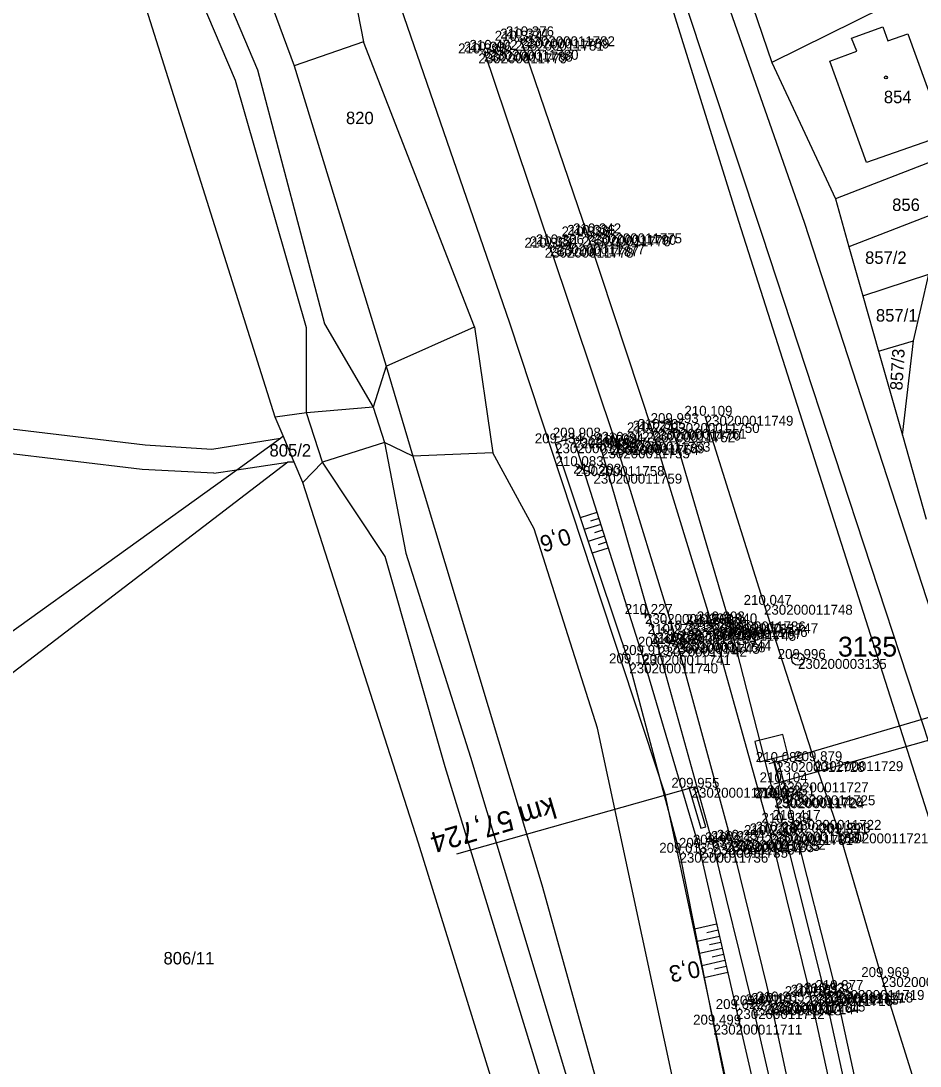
# Model space of a CAD drawing. Extents: x -563148 to -561712, y -1182311 to -1179502.
# Drawn here: x -562800.9 to -562692.4, y -1179961.9 to -1179835.6 of the extents above; entities that cross this region are included whole.
import ezdxf

# ---------------------------------------------------------------- set-up
doc = ezdxf.new("R2010")
doc.units = 0
for name, color, linetype in [('Vrstva 1', 7, 'Continuous'), ('Vrstva 14', 7, 'Continuous'), ('Vrstva 23', 7, 'Continuous'), ('Vrstva 4', 7, 'Continuous'), ('Vrstva 48', 7, 'Continuous'), ('Vrstva 49', 7, 'Continuous'), ('Vrstva 53', 7, 'Continuous'), ('Vrstva 55', 7, 'Continuous'), ('Vrstva 56', 7, 'Continuous'), ('Vrstva 57', 7, 'Continuous'), ('Vrstva 60', 7, 'Continuous'), ('Vrstva 61', 7, 'Continuous'), ('Vrstva 63', 7, 'Continuous'), ('Vrstva 7', 7, 'Continuous'), ('Vrstva 9', 7, 'Continuous')]:
    doc.layers.add(name, color=color, linetype=linetype)

msp = doc.modelspace()

# ---------------------------------------------------------------- linework, layer by layer
at = {"layer": 'Vrstva 1'}
for points in [[(-562740.6, -1179837.77), (-562732.51, -1179861.48), (-562724.71, -1179885.12), (-562717.35, -1179909.07), (-562710.47, -1179933.75), (-562705.64, -1179953.24), (-562700.21, -1179978.17), (-562696.2, -1179999.76), (-562692.55, -1180023.18), (-562689.41, -1180047.36), (-562687.1, -1180067.31), (-562684.6, -1180089.77), (-562682.01, -1180113.42)], [(-562745.01, -1179839.35), (-562737.06, -1179862.87), (-562729.09, -1179886.66), (-562721.74, -1179910.68), (-562715.17, -1179934.68), (-562710.39, -1179954.23), (-562705.02, -1179979.2), (-562701.02, -1180000.75), (-562697.43, -1180023.66), (-562694.26, -1180047.81), (-562691.92, -1180067.92), (-562689.44, -1180090.3), (-562686.84, -1180113.86)]]:
    msp.add_lwpolyline(points, dxfattribs=at)
at = {"layer": 'Vrstva 14'}
msp.add_lwpolyline([(-562708.48, -1179929.16), (-562709.81, -1179929.52), (-562709.06, -1179932.48), (-562703.91, -1179952.98), (-562698.53, -1179977.59), (-562694.4, -1179999.84), (-562690.74, -1180023.29), (-562687.63, -1180047.31), (-562685.27, -1180067.34), (-562682.92, -1180089.43), (-562680.17, -1180114.48), (-562679.62, -1180119.47), (-562678.23, -1180119.28), (-562678.8, -1180114.3), (-562681.54, -1180089.23), (-562683.88, -1180067.22), (-562686.25, -1180047.12), (-562689.37, -1180023.01), (-562693.01, -1179999.73), (-562697.19, -1179977.32), (-562702.55, -1179952.67), (-562707.74, -1179932.13), (-562708.48, -1179929.16)], dxfattribs=at)
at = {"layer": 'Vrstva 23'}
msp.add_line((-562733.93, -1179889.41), (-562731.8, -1179890.32), dxfattribs=at)
at = {"layer": 'Vrstva 4'}
for points in [[(-562722.45, -1179884.21), (-562715.38, -1179908.39), (-562709.97, -1179929.42)], [(-562683.72, -1180156.67), (-562685.94, -1180137.11), (-562688.4, -1180114.59), (-562691.08, -1180090.75), (-562693.51, -1180068.13), (-562695.85, -1180048.01), (-562699.08, -1180023.86), (-562701.31, -1180009.06), (-562702.78, -1180000.96), (-562706.81, -1179979.53), (-562712.56, -1179954.53), (-562717.35, -1179935.12), (-562723.98, -1179911.21), (-562730.87, -1179887.27)]]:
    msp.add_lwpolyline(points, dxfattribs=at)
at = {"layer": 'Vrstva 48'}
for p, q in [((-562731.39, -1179895.01), (-562733.4, -1179895.65)), ((-562731.16, -1179895.73), (-562732.16, -1179896.04)), ((-562730.93, -1179896.44), (-562732.92, -1179897.07)), ((-562730.48, -1179897.87), (-562732.44, -1179898.49)), ((-562730.71, -1179897.16), (-562731.69, -1179897.47)), ((-562730.03, -1179899.3), (-562731.96, -1179899.91)), ((-562730.25, -1179898.59), (-562731.22, -1179898.9)), ((-562716.93, -1179944.73), (-562719.59, -1179945.33)), ((-562716.6, -1179946.19), (-562719.3, -1179946.8)), ((-562716.76, -1179945.46), (-562718.1, -1179945.76)), ((-562716.43, -1179946.92), (-562717.79, -1179947.23)), ((-562716.26, -1179947.65), (-562719.01, -1179948.28)), ((-562716.09, -1179948.38), (-562717.48, -1179948.7)), ((-562715.93, -1179949.11), (-562718.72, -1179949.75)), ((-562715.76, -1179949.84), (-562717.17, -1179950.16)), ((-562715.59, -1179950.57), (-562718.43, -1179951.22))]:
    msp.add_line(p, q, dxfattribs=at)
at = {"layer": 'Vrstva 49'}
for points in [[(-562718.37, -1179883.33), (-562711.21, -1179906.16), (-562705.11, -1179925.04), (-562702.08, -1179933.76), (-562697.02, -1179951.11), (-562689.45, -1179975.3), (-562684.23, -1179997.89)], [(-562734.26, -1179885.96), (-562736.43, -1179886.65), (-562727.47, -1179913.23), (-562721.41, -1179936.1), (-562717.31, -1179956.85), (-562712.51, -1179980.34), (-562708.84, -1179979.83)], [(-562734.26, -1179885.96), (-562725.93, -1179912.22), (-562719.03, -1179935.5), (-562714.59, -1179954.97), (-562708.84, -1179979.83)]]:
    msp.add_lwpolyline(points, dxfattribs=at)
at = {"layer": 'Vrstva 53'}
for p, q in [((-562726.49, -1179820.62), (-562714.28, -1179859.84)), ((-562741.88, -1179872.14), (-562755.69, -1179832.1)), ((-562714.28, -1179859.84), (-562686.66, -1179946.58)), ((-562723.16, -1179929.01), (-562741.88, -1179872.14)), ((-562708.95, -1179995.64), (-562723.16, -1179929.01))]:
    msp.add_line(p, q, dxfattribs=at)
at = {"layer": 'Vrstva 55'}
for p, q in [((-562770.21, -1179883.48), (-562789.53, -1179822.31)), ((-562771.87, -1179830.41), (-562767.94, -1179841.07)), ((-562712.55, -1179833.93), (-562710.25, -1179840.66)), ((-562696.76, -1179834), (-562710.25, -1179840.66)), ((-562700.64, -1179837.73), (-562696.86, -1179836.37)), ((-562696.86, -1179836.37), (-562696.27, -1179838.05)), ((-562699.99, -1179839.29), (-562700.64, -1179837.73)), ((-562696.27, -1179838.05), (-562693.84, -1179837.19)), ((-562693.84, -1179837.19), (-562689.44, -1179849.44)), ((-562759.58, -1179838.16), (-562767.94, -1179841.07)), ((-562746.18, -1179872.58), (-562759.58, -1179838.16)), ((-562703.26, -1179840.49), (-562699.99, -1179839.29)), ((-562767.94, -1179841.07), (-562756.81, -1179877.33)), ((-562710.25, -1179840.66), (-562702.59, -1179857.13)), ((-562698.83, -1179852.76), (-562703.26, -1179840.49)), ((-562689.44, -1179849.44), (-562698.83, -1179852.76)), ((-562687.51, -1179851.29), (-562702.59, -1179857.13)), ((-562702.59, -1179857.13), (-562700.96, -1179862.91)), ((-562689.54, -1179858.51), (-562700.96, -1179862.91)), ((-562700.96, -1179862.91), (-562699.28, -1179868.83)), ((-562699.28, -1179868.83), (-562691.31, -1179866.24)), ((-562693.16, -1179874.28), (-562691.31, -1179866.24)), ((-562699.28, -1179868.83), (-562697.39, -1179875.51)), ((-562756.81, -1179877.33), (-562746.18, -1179872.58)), ((-562697.39, -1179875.51), (-562693.16, -1179874.28)), ((-562694.51, -1179885.66), (-562693.16, -1179874.28)), ((-562697.39, -1179875.51), (-562694.51, -1179885.66)), ((-562868.6, -1179877.08), (-562785.92, -1179886.82)), ((-562756.81, -1179877.33), (-562753.62, -1179888.19)), ((-562786.27, -1179889.8), (-562868.86, -1179880.06)), ((-562769.26, -1179885.74), (-562770.21, -1179883.48)), ((-562769.57, -1179886.05), (-562769.26, -1179885.74)), ((-562767.92, -1179888.92), (-562769.26, -1179885.74)), ((-562694.51, -1179885.66), (-562691.64, -1179895.8)), ((-562785.92, -1179886.82), (-562777.87, -1179887.35)), ((-562777.87, -1179887.35), (-562769.57, -1179886.05)), ((-562774.86, -1179889.85), (-562769.57, -1179886.05)), ((-562743.96, -1179887.8), (-562753.62, -1179888.19)), ((-562753.62, -1179888.19), (-562738.04, -1179939.96)), ((-562738.97, -1179896.97), (-562743.96, -1179887.8)), ((-562768.68, -1179888.92), (-562835.68, -1179940.17)), ((-562774.86, -1179889.85), (-562768.68, -1179888.92)), ((-562767.92, -1179888.92), (-562768.68, -1179888.92)), ((-562766.88, -1179891.39), (-562767.92, -1179888.92)), ((-562839.45, -1179936.26), (-562774.86, -1179889.85)), ((-562777.64, -1179890.27), (-562786.27, -1179889.8)), ((-562777.64, -1179890.27), (-562774.86, -1179889.85)), ((-562752.94, -1179934.93), (-562766.88, -1179891.39)), ((-562731.33, -1179921.05), (-562738.97, -1179896.97)), ((-562716.52, -1179989.81), (-562731.33, -1179921.05)), ((-562736.47, -1179988), (-562752.94, -1179934.93)), ((-562738.04, -1179939.96), (-562723.97, -1179990.65))]:
    msp.add_line(p, q, dxfattribs=at)
at = {"layer": 'Vrstva 56'}
for p, q in [((-562788.49, -1179803.34), (-562772.35, -1179841.57)), ((-562775.02, -1179842.84), (-562791.27, -1179804.7)), ((-562720.72, -1179818.86), (-562706.35, -1179859.95)), ((-562711.42, -1179861.45), (-562725.13, -1179820.2)), ((-562761.97, -1179825.83), (-562759.58, -1179838.16)), ((-562772.35, -1179841.57), (-562764.29, -1179872.23)), ((-562766.45, -1179872.71), (-562775.02, -1179842.84)), ((-562706.35, -1179859.95), (-562678.76, -1179945.02)), ((-562683.71, -1179946), (-562711.42, -1179861.45)), ((-562766.44, -1179882.98), (-562766.45, -1179872.71)), ((-562764.29, -1179872.23), (-562758.38, -1179882.28)), ((-562746.18, -1179872.58), (-562743.96, -1179887.8)), ((-562756.81, -1179877.33), (-562758.38, -1179882.28)), ((-562766.44, -1179882.98), (-562770.21, -1179883.48)), ((-562758.38, -1179882.28), (-562766.44, -1179882.98)), ((-562764.52, -1179888.92), (-562766.44, -1179882.98)), ((-562758.38, -1179882.28), (-562757.03, -1179886.57)), ((-562757.03, -1179886.57), (-562764.52, -1179888.92)), ((-562753.62, -1179888.19), (-562757.03, -1179886.57)), ((-562757.03, -1179886.57), (-562754.44, -1179899.9)), ((-562764.52, -1179888.92), (-562766.88, -1179891.39)), ((-562756.93, -1179900.31), (-562764.52, -1179888.92)), ((-562749.69, -1179925.73), (-562756.93, -1179900.31)), ((-562754.44, -1179899.9), (-562746.63, -1179924.55)), ((-562746.63, -1179924.55), (-562733.41, -1179968.62)), ((-562736.38, -1179969.25), (-562749.69, -1179925.73))]:
    msp.add_line(p, q, dxfattribs=at)
at = {"layer": 'Vrstva 57'}
msp.add_circle((-562696.49, -1179842.47), 0.175, dxfattribs=at)
at = {"layer": 'Vrstva 60'}
for p, q in [((-562740.6, -1179837.77), (-562740.6, -1179837.77)), ((-562739.92, -1179837.5), (-562739.92, -1179837.5)), ((-562741.27, -1179838.03), (-562741.27, -1179838.03)), ((-562745.69, -1179839.57), (-562745.69, -1179839.57)), ((-562745.01, -1179839.35), (-562745.01, -1179839.35)), ((-562744.32, -1179839.14), (-562744.32, -1179839.14)), ((-562733.2, -1179861.67), (-562733.2, -1179861.67)), ((-562732.51, -1179861.48), (-562732.51, -1179861.48)), ((-562731.82, -1179861.3), (-562731.82, -1179861.3)), ((-562737.68, -1179863.03), (-562737.68, -1179863.03)), ((-562737.06, -1179862.87), (-562737.06, -1179862.87)), ((-562736.29, -1179862.63), (-562736.29, -1179862.63)), ((-562722.45, -1179884.21), (-562722.45, -1179884.21)), ((-562718.37, -1179883.33), (-562718.37, -1179883.33)), ((-562725.4, -1179885.33), (-562725.4, -1179885.33)), ((-562724.71, -1179885.12), (-562724.71, -1179885.12)), ((-562724.01, -1179884.92), (-562724.01, -1179884.92)), ((-562736.43, -1179886.65), (-562736.43, -1179886.65)), ((-562734.26, -1179885.96), (-562734.26, -1179885.96)), ((-562729.79, -1179886.85), (-562729.79, -1179886.85)), ((-562729.09, -1179886.66), (-562729.09, -1179886.66)), ((-562728.39, -1179886.47), (-562728.39, -1179886.47)), ((-562730.87, -1179887.27), (-562730.87, -1179887.27)), ((-562733.93, -1179889.41), (-562733.93, -1179889.41)), ((-562731.8, -1179890.32), (-562731.8, -1179890.32)), ((-562711.21, -1179906.16), (-562711.21, -1179906.16)), ((-562725.57, -1179907.26), (-562725.57, -1179907.26)), ((-562716.88, -1179908.16), (-562716.88, -1179908.16)), ((-562715.38, -1179908.39), (-562715.38, -1179908.39)), ((-562722.8, -1179909.67), (-562722.8, -1179909.67)), ((-562721.42, -1179909.26), (-562721.42, -1179909.26)), ((-562718.29, -1179908.5), (-562718.29, -1179908.5)), ((-562718.04, -1179909.29), (-562718.04, -1179909.29)), ((-562717.35, -1179909.07), (-562717.35, -1179909.07)), ((-562716.66, -1179908.84), (-562716.66, -1179908.84)), ((-562722.44, -1179910.87), (-562722.44, -1179910.87)), ((-562721.74, -1179910.68), (-562721.74, -1179910.68)), ((-562721.05, -1179910.5), (-562721.05, -1179910.5)), ((-562725.93, -1179912.22), (-562725.93, -1179912.22)), ((-562723.98, -1179911.21), (-562723.98, -1179911.21)), ((-562727.47, -1179913.23), (-562727.47, -1179913.23)), ((-562707.11, -1179912.69), (-562707.11, -1179912.69)), ((-562709.75, -1179925.14), (-562709.75, -1179925.14)), ((-562705.11, -1179925.04), (-562705.11, -1179925.04)), ((-562719.95, -1179928.25), (-562719.95, -1179928.25)), ((-562709.29, -1179927.59), (-562709.29, -1179927.59)), ((-562709.97, -1179929.42), (-562709.97, -1179929.42)), ((-562709.81, -1179929.52), (-562709.81, -1179929.52)), ((-562708.48, -1179929.16), (-562708.48, -1179929.16)), ((-562707.74, -1179932.13), (-562707.74, -1179932.13)), ((-562709.78, -1179933.56), (-562709.78, -1179933.56)), ((-562709.06, -1179932.48), (-562709.06, -1179932.48)), ((-562715.88, -1179934.82), (-562715.88, -1179934.82)), ((-562715.17, -1179934.68), (-562715.17, -1179934.68)), ((-562714.46, -1179934.53), (-562714.46, -1179934.53)), ((-562711.17, -1179933.95), (-562711.17, -1179933.95)), ((-562710.47, -1179933.75), (-562710.47, -1179933.75)), ((-562702.08, -1179933.76), (-562702.08, -1179933.76)), ((-562721.41, -1179936.1), (-562721.41, -1179936.1)), ((-562719.03, -1179935.5), (-562719.03, -1179935.5)), ((-562717.35, -1179935.12), (-562717.35, -1179935.12)), ((-562697.02, -1179951.11), (-562697.02, -1179951.11)), ((-562702.55, -1179952.67), (-562702.55, -1179952.67)), ((-562706.34, -1179953.41), (-562706.34, -1179953.41)), ((-562705.64, -1179953.24), (-562705.64, -1179953.24)), ((-562704.93, -1179953.07), (-562704.93, -1179953.07)), ((-562703.91, -1179952.98), (-562703.91, -1179952.98)), ((-562714.59, -1179954.97), (-562714.59, -1179954.97)), ((-562712.56, -1179954.53), (-562712.56, -1179954.53)), ((-562711.1, -1179954.39), (-562711.1, -1179954.39)), ((-562710.39, -1179954.23), (-562710.39, -1179954.23)), ((-562709.68, -1179954.06), (-562709.68, -1179954.06)), ((-562717.31, -1179956.85), (-562717.31, -1179956.85))]:
    msp.add_line(p, q, dxfattribs=at)
at = {"layer": 'Vrstva 63'}
msp.add_line((-562707.16, -1179912.69), (-562707.06, -1179912.69), dxfattribs=at)
msp.add_circle((-562707.11, -1179912.69), 0.756, dxfattribs=at)
at = {"layer": 'Vrstva 7'}
for p, q in [((-562725.57, -1179906.76), (-562725.57, -1179907.76)), ((-562726.07, -1179907.26), (-562725.07, -1179907.26)), ((-562709.29, -1179927.59), (-562674.34, -1179917.65)), ((-562710.02, -1179927.77), (-562708.57, -1179927.4))]:
    msp.add_line(p, q, dxfattribs=at)
msp.add_lwpolyline([(-562709.29, -1179927.59), (-562710.03, -1179924.68), (-562708.33, -1179924.25), (-562708.94, -1179921.83), (-562712.33, -1179922.68), (-562711.72, -1179925.1), (-562710.03, -1179924.68)], dxfattribs=at)
at = {"layer": 'Vrstva 9'}
for p, q in [((-562709.75, -1179925.14), (-562675.7, -1179915.15)), ((-562710.04, -1179925.21), (-562710.62, -1179925.36)), ((-562709.46, -1179925.06), (-562710.04, -1179925.21)), ((-562710.04, -1179925.21), (-562708.81, -1179930.06)), ((-562708.23, -1179929.91), (-562709.46, -1179925.06)), ((-562719.95, -1179928.25), (-562748.33, -1179936.25)), ((-562720.24, -1179928.34), (-562720.81, -1179928.51)), ((-562719.66, -1179928.17), (-562720.24, -1179928.34)), ((-562720.24, -1179928.34), (-562718.82, -1179933.13)), ((-562718.24, -1179932.96), (-562719.66, -1179928.17)), ((-562708.81, -1179930.06), (-562708.23, -1179929.91)), ((-562718.82, -1179933.13), (-562718.24, -1179932.96))]:
    msp.add_line(p, q, dxfattribs=at)

# ---------------------------------------------------------------- texts
at = {"layer": 'Vrstva 48'}
for s, rotation, p in [('0,6', 197.5951, (-562734.91, -1179896.84)), ('0,3', 191.1734, (-562719.16, -1179949.1))]:
    msp.add_text(s, height=2, rotation=rotation, dxfattribs=at).set_placement(p)
at = {"layer": 'Vrstva 57'}
for s, p in [('854', (-562696.74, -1179845.58)), ('820', (-562761.68, -1179848.11)), ('856', (-562695.74, -1179858.59)), ('857/2', (-562699.01, -1179864.98)), ('857/1', (-562697.7, -1179871.95)), ('805/2', (-562770.91, -1179888.25)), ('806/11', (-562783.71, -1179949.58))]:
    msp.add_text(s, height=1.5, dxfattribs=at).set_placement(p)
msp.add_text('857/3', height=1.5, rotation=86.6336, dxfattribs=at).set_placement((-562694.51, -1179880.29))
at = {"layer": 'Vrstva 60'}
for s, p in [('230200011789', (-562740.6, -1179838.97)), ('230200011782', (-562739.92, -1179838.7)), ('230200011781', (-562741.27, -1179839.23)), ('230200011779', (-562745.69, -1179840.77)), ('230200011788', (-562745.01, -1179840.55)), ('230200011780', (-562744.32, -1179840.34)), ('230200011776', (-562733.2, -1179862.87)), ('230200011790', (-562732.51, -1179862.68)), ('230200011775', (-562731.82, -1179862.5)), ('230200011778', (-562737.68, -1179864.23)), ('230200011787', (-562737.06, -1179864.07)), ('230200011777', (-562736.29, -1179863.83)), ('230200011750', (-562722.45, -1179885.41)), ('230200011749', (-562718.37, -1179884.53)), ('230200011752', (-562725.4, -1179886.53)), ('230200011770', (-562724.71, -1179886.32)), ('230200011751', (-562724.01, -1179886.11)), ('230200011757', (-562736.43, -1179887.85)), ('230200011756', (-562734.26, -1179887.16)), ('230200011754', (-562729.79, -1179888.05)), ('230200011769', (-562729.09, -1179887.86)), ('230200011753', (-562728.39, -1179887.67)), ('230200011755', (-562730.87, -1179888.47)), ('230200011758', (-562733.93, -1179890.61)), ('230200011759', (-562731.8, -1179891.52)), ('230200011748', (-562711.21, -1179907.35)), ('230200011760', (-562725.57, -1179908.46)), ('230200011785', (-562718.29, -1179909.7)), ('230200011786', (-562716.88, -1179909.36)), ('230200011747', (-562715.38, -1179909.59)), ('230200011783', (-562722.8, -1179910.87)), ('230200011784', (-562721.42, -1179910.46)), ('230200011745', (-562718.04, -1179910.5)), ('230200011767', (-562717.35, -1179910.27)), ('230200011746', (-562716.66, -1179910.04)), ('230200011743', (-562722.44, -1179912.07)), ('230200011768', (-562721.74, -1179911.88)), ('230200011744', (-562721.05, -1179911.7)), ('230200011741', (-562725.93, -1179913.42)), ('230200011742', (-562723.98, -1179912.41)), ('230200011740', (-562727.47, -1179914.43)), ('230200003135', (-562707.11, -1179913.89)), ('230200011728', (-562709.75, -1179926.33)), ('230200011729', (-562705.11, -1179926.24)), ('230200011739', (-562719.95, -1179929.45)), ('230200011727', (-562709.29, -1179928.79)), ('230200011726', (-562709.97, -1179930.62)), ('230200011724', (-562709.81, -1179930.72)), ('230200011725', (-562708.48, -1179930.36)), ('230200011723', (-562709.06, -1179933.68)), ('230200011722', (-562707.74, -1179933.33)), ('230200011766', (-562710.47, -1179934.95)), ('230200011730', (-562709.78, -1179934.76)), ('230200011733', (-562715.88, -1179936.02)), ('230200011765', (-562715.17, -1179935.88)), ('230200011732', (-562714.46, -1179935.73)), ('230200011731', (-562711.17, -1179935.15)), ('230200011721', (-562702.08, -1179934.96)), ('230200011736', (-562721.41, -1179937.3)), ('230200011735', (-562719.03, -1179936.7)), ('230200011734', (-562717.35, -1179936.32)), ('230200011720', (-562697.02, -1179952.31)), ('230200011719', (-562702.55, -1179953.87)), ('230200011716', (-562706.34, -1179954.61)), ('230200011763', (-562705.64, -1179954.44)), ('230200011717', (-562704.93, -1179954.27)), ('230200011718', (-562703.91, -1179954.18)), ('230200011712', (-562714.59, -1179956.17)), ('230200011713', (-562712.56, -1179955.73)), ('230200011714', (-562711.1, -1179955.59)), ('230200011764', (-562710.39, -1179955.43)), ('230200011715', (-562709.68, -1179955.27)), ('230200011711', (-562717.31, -1179958.05))]:
    msp.add_text(s, height=1.2, dxfattribs=at).set_placement(p)
at = {"layer": 'Vrstva 61'}
for s, p in [('210.374', (-562743.05, -1179837.77)), ('210.376', (-562742.37, -1179837.5)), ('210.374', (-562743.72, -1179838.03)), ('210.396', (-562748.14, -1179839.57)), ('210.396', (-562747.46, -1179839.35)), ('210.402', (-562746.77, -1179839.14)), ('210.336', (-562735.65, -1179861.67)), ('210.336', (-562734.96, -1179861.48)), ('210.342', (-562734.26, -1179861.3)), ('210.354', (-562739.51, -1179862.87)), ('210.366', (-562738.75, -1179862.63)), ('210.354', (-562740.13, -1179863.03)), ('209.993', (-562724.9, -1179884.21)), ('210.109', (-562720.82, -1179883.33)), ('210.271', (-562727.76, -1179885.33)), ('210.271', (-562727.07, -1179885.12)), ('210.305', (-562726.47, -1179884.92)), ('209.434', (-562738.88, -1179886.65)), ('209.908', (-562736.71, -1179885.96)), ('210.284', (-562732.24, -1179886.85)), ('210.284', (-562731.54, -1179886.66)), ('210.312', (-562730.84, -1179886.47)), ('210.043', (-562733.32, -1179887.27)), ('210.083', (-562736.38, -1179889.41)), ('210.293', (-562734.25, -1179890.32)), ('210.047', (-562713.67, -1179906.16)), ('210.227', (-562728.02, -1179907.26)), ('210.298', (-562719.33, -1179908.16)), ('209.940', (-562717.83, -1179908.39)), ('210.272', (-562725.25, -1179909.67)), ('210.311', (-562723.77, -1179909.26)), ('210.261', (-562720.64, -1179908.5)), ('210.243', (-562720.49, -1179909.29)), ('210.243', (-562719.8, -1179909.07)), ('210.279', (-562719.12, -1179908.84)), ('210.248', (-562724.89, -1179910.87)), ('210.248', (-562724.19, -1179910.68)), ('210.287', (-562723.5, -1179910.5)), ('209.919', (-562728.38, -1179912.22)), ('209.953', (-562726.43, -1179911.21)), ('209.120', (-562729.92, -1179913.23)), ('209.996', (-562709.56, -1179912.69)), ('210.089', (-562712.2, -1179925.14)), ('209.879', (-562707.56, -1179925.04)), ('209.955', (-562722.4, -1179928.25)), ('210.104', (-562711.74, -1179927.59)), ('210.084', (-562712.42, -1179929.42)), ('210.376', (-562712.26, -1179929.52)), ('210.251', (-562710.84, -1179929.16)), ('210.417', (-562710.19, -1179932.13)), ('210.244', (-562712.23, -1179933.56)), ('210.539', (-562711.52, -1179932.48)), ('210.213', (-562718.33, -1179934.82)), ('210.213', (-562717.62, -1179934.68)), ('210.254', (-562716.91, -1179934.53)), ('210.210', (-562713.62, -1179933.95)), ('210.210', (-562712.93, -1179933.75)), ('209.891', (-562704.44, -1179933.76)), ('209.013', (-562723.86, -1179936.1)), ('209.783', (-562721.48, -1179935.5)), ('209.953', (-562719.8, -1179935.12)), ('209.969', (-562699.47, -1179951.11)), ('210.181', (-562708.7, -1179953.41)), ('210.181', (-562707.99, -1179953.24)), ('210.232', (-562707.38, -1179953.07)), ('210.532', (-562706.36, -1179952.98)), ('210.377', (-562705.01, -1179952.67)), ('209.622', (-562717.04, -1179954.97)), ('209.877', (-562715.01, -1179954.53)), ('210.191', (-562713.46, -1179954.39)), ('210.191', (-562712.75, -1179954.23)), ('210.235', (-562712.13, -1179954.06)), ('209.499', (-562719.77, -1179956.85))]:
    msp.add_text(s, height=1.2, dxfattribs=at).set_placement(p)
at = {"layer": 'Vrstva 63'}
msp.add_text('3135', height=2.4, dxfattribs=at).set_placement((-562702.28, -1179912.41))
at = {"layer": 'Vrstva 9'}
msp.add_text('km 57,724', height=2.5, rotation=196.5001, dxfattribs=at).set_placement((-562736.75, -1179929.34))

doc.saveas('drawing.dxf')
